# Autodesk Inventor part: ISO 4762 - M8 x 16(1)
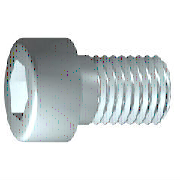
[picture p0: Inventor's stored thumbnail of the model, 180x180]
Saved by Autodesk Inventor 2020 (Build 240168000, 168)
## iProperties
Created: 2019-01
Part Number: ISO 4762 - M8 x 16(1)
Material: Nerezová ocel 440C
Description: Šroub s válcovou hlavou s vnitřním šestihranem
Document SubType Name: Modeling
Standard: ISO 4762
Designer: doma
Standard Revision: Fourth edition 2004-03-01
Standards Organization: ISO
Language: cs-CZ
Size Designation: M8 x 16
Categories: <MemberInstance><Categories><Category DisplayName="Spojovací materiál" InternalName="e4da775c-781d-43d5-af7c-5136215cf5a6" Mnemonic="FSTN"><Category DisplayName
Density: 7.75 g/cm^3
Appearance: Pololeštěná
IsCustomPart: 0
Author: doma
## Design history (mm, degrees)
sketch "Náčrt1"
  geometry: L1 (-2, 0)-(16, 0); L2 (16, 0)-(16, 4); L3 (16, 4)-(3.125, 4); L4 (3.125, 4)-(2.358, 4); L5 (2.358, 4)-(0, 4); L6 (0, 4)-(0, 6.5); L7 (0, 6.5)-(-8, 6.5); L8 (-8, 6.5)-(-8, 3.464); L9 (-8, 3.464)-(-4, 3.464); L10 (-4, 3.464)-(-2, 0); L11 (-12.8, 0)-(20.8, 0) reference; L12 (0, -1.3)-(0, 7.8) reference; L13 (3.125, 4)-(0, 4)
  constraints: 22 end point, 6 parallel, 2 collinear, 2 perpendicular, 1 horizontal, 1 point on line
  dimensions: "d1" = 12.875 distance from line of L3.end L2 (= GEL); "d2" = 0.76691 distance of L4.end L3.end (computed from GAL); "d3" = 8 distance between parallel lines of L8 L6 (= KOH); "d4" = 4 distance of L8.end L9.end (= INTI); "d5" = 60 deg angle of L10 L1; "d6" = 8 diameter of L3 L1 (= GD); "d7" = 8 diameter of L5 L1 (= BDM); "d8" = 6.9282 diameter of L9 L1 (= 1.1547 x SW); "d9" = 13 diameter of L7 L1 (= KOD); "d26" = 16 distance between parallel lines of L12 L2 (= NLG)
revolve "Těleso" sketch "Náčrt1" stored, may be unused: angle "d10" = 90 deg
sketch "Náčrt2"
  geometry: L1 (0, -9.1)-(0, 9.1) reference; L2 (-9.1, 0)-(9.1, 0) reference; L3 (3.464, 0)-(1.732, -3); L4 (1.732, -3)-(-1.732, -3); L5 (-1.732, -3)-(-3.464, 0); L6 (-3.464, 0)-(-1.732, 3); L7 (-1.732, 3)-(1.732, 3); L8 (1.732, 3)-(3.464, 0); 2 further points
  constraints: 12 end point, 1 coincident, 1 horizontal alignment, 1 point on line, 12 other
extrude "Drážka" join sketch "Náčrt2" stored distance "d11" = 10; taper "d12" = 0 deg
workplane "Work Plane1"
fillet "Fillet2" dims "d30" = 0.1 (= R)
body "Solid1"
fillet "Zaoblení1" dims "d17" = 0.8 (= RR)
feature "Závit" dims "d13" = 12.875 (= GEL), "d14" = 0
chamfer "Zkosení1" distance "d15" = 0.76681 (= -0.5 x SPD + 0.5 x GD); stored, may be unused: second distance "d16" = 0.76681 (= GUL), angle "d27" = 45 deg
other parameters: "GD" = 8 [user parameter; used in 2 equation terms], "NLG" = 16 [user parameter; used in 1 equation term], "GEL" = 12.875 [user parameter; used in 2 equation terms], "KOD" = 13 [user parameter; used in 1 equation term], "KOH" = 8 [user parameter; used in 1 equation term], "INTI" = 4 [user parameter; used in 1 equation term], "GAL" = 0.76681 (= 0.61345 x PTC) [user parameter; used in 1 equation term], "GUL" = 0.76681 (= 0.61345 x PTC) [user parameter; used in 1 equation term], "BDM" = 8 (= NND) [user parameter; used in 1 equation term], "SW" = 6 [user parameter; used in 2 equation terms], "RR" = 0.8 [user parameter; used in 1 equation term], "SPD" = 6.46637 (= NND - 1.2269 x PTC) [user parameter; used in 1 equation term], "d19" = 0, "d28" = 0, "d29" = 0, "R" = 0.1 [user parameter; used in 1 equation term], "TOA" = 30 deg [user parameter], "GD1" = 6.46637 (= THREADDIA - 1.2269 x PTC) [user parameter], "THREADDIA" = 8 [user parameter; used in 1 equation term], "FAWI" = 45 deg [user parameter], "TPU" = 8 (computed from PTC) [user parameter], "PTC" = 1.25 [user parameter; used in 5 equation terms], "NND" = 8 [user parameter; used in 2 equation terms], "E0" = 6.93 (= 1.155 x SW) [user parameter]
